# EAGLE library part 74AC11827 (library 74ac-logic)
10-bit BUFFER/BUS DRIVER, 3-state
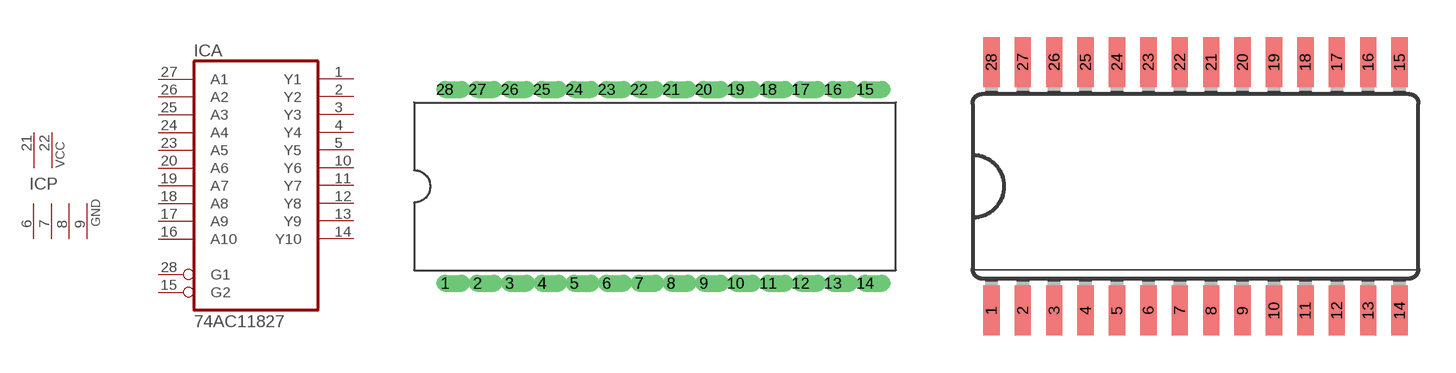
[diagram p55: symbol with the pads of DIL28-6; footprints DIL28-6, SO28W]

Designator prefix IC; gates A=7411827 P=2PWR4GND

## 74AC11827  [DIL28-6]
1  A:Y1  hiz
2  A:Y2  hiz
3  A:Y3  hiz
4  A:Y4  hiz
5  A:Y5  hiz
6  P:GND  pwr
7  P:GND  pwr
8  P:GND  pwr
9  P:GND  pwr
10  A:Y6  hiz
11  A:Y7  hiz
12  A:Y8  hiz
13  A:Y9  hiz
14  A:Y10  hiz
15  A:G2  in
16  A:A10  in
17  A:A9  in
18  A:A8  in
19  A:A7  in
20  A:A6  in
21  P:VCC  pwr
22  P:VCC  pwr
23  A:A5  in
24  A:A4  in
25  A:A3  in
26  A:A2  in
27  A:A1  in
28  A:G1  in

## 74AC11827D  [SO28W]
Pads as for DIL28-6

## Footprint DIL28-6 (pad centres in mm)
Dual In Line 0.6 inch
drill 0.813 offset: 1 -16.51,-7.62; 2 -13.97,-7.62; 3 -11.43,-7.62; 4 -8.89,-7.62; 5 -6.35,-7.62; 6 -3.81,-7.62; 7 -1.27,-7.62; 8 1.27,-7.62; 9 3.81,-7.62; 10 6.35,-7.62; 11 8.89,-7.62; 12 11.43,-7.62; 13 13.97,-7.62; 14 16.51,-7.62; 15 16.51,7.62; 16 13.97,7.62; 17 11.43,7.62; 18 8.89,7.62; 19 6.35,7.62; 20 3.81,7.62; 21 1.27,7.62; 22 -1.27,7.62; 23 -3.81,7.62; 24 -6.35,7.62; 25 -8.89,7.62; 26 -11.43,7.62; 27 -13.97,7.62; 28 -16.51,7.62

## Footprint SO28W (pad centres in mm)
Wide Small Outline package 300 mil
smd 0.66 x 2.032: 1 -8.255,-5.029; 2 -6.985,-5.029; 3 -5.715,-5.029; 4 -4.445,-5.029; 5 -3.175,-5.029; 6 -1.905,-5.029; 7 -0.635,-5.029; 8 0.635,-5.029; 9 1.905,-5.029; 10 3.175,-5.029; 11 4.445,-5.029; 12 5.715,-5.029; 13 6.985,-5.029; 14 8.255,-5.029; 15 8.255,5.029; 16 6.985,5.029; 17 5.715,5.029; 18 4.445,5.029; 19 3.175,5.029; 20 1.905,5.029; 21 0.635,5.029; 22 -0.635,5.029; 23 -1.905,5.029; 24 -3.175,5.029; 25 -4.445,5.029; 26 -5.715,5.029; 27 -6.985,5.029; 28 -8.255,5.029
